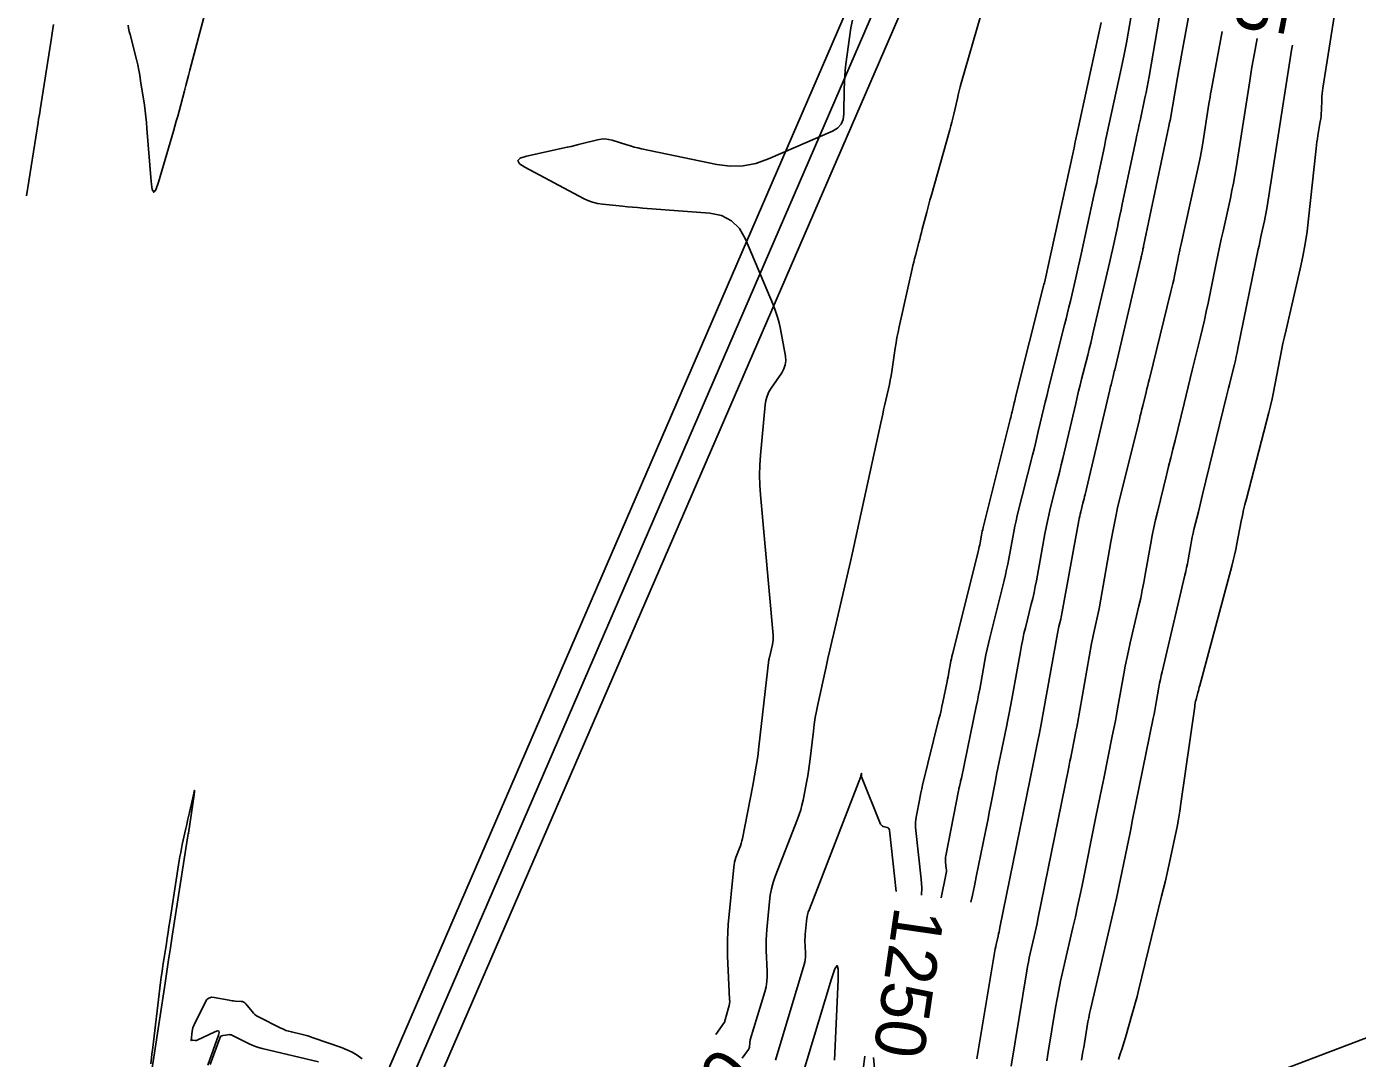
# Model space of a CAD drawing. Extents: x 658976 to 668721, y 639543 to 647196.
# Drawn here: x 661518.4 to 661677.1, y 641635 to 641758.1 of the extents above; entities that cross this region are included whole.
import ezdxf

# ---------------------------------------------------------------- set-up
doc = ezdxf.new("R2010")
doc.units = 0
for name, color, linetype in [('Ex_Contour Labels', 7, 'Continuous'), ('Ex_Major Contours', 7, 'Continuous'), ('Ex_Minor Contours', 7, 'Continuous'), ('R_Water', 7, 'Continuous')]:
    doc.layers.add(name, color=color, linetype=linetype)

msp = doc.modelspace()

# ---------------------------------------------------------------- linework, layer by layer
at = {"layer": 'Ex_Major Contours'}
for points in [[(661603.77, 641635.03), (661604.51, 641636.08), (661604.56, 641636.16), (661604.6, 641636.25), (661604.63, 641636.34), (661604.64, 641636.44), (661604.66, 641636.83), (661604.67, 641636.93), (661604.69, 641637.03), (661604.71, 641637.12), (661604.73, 641637.22), (661606.46, 641642.97), (661606.61, 641643.57), (661606.72, 641644.18), (661606.76, 641644.79), (661606.76, 641645.41), (661606.64, 641647.9), (661606.62, 641648.52), (661606.63, 641649.15), (661606.65, 641649.77), (661606.7, 641650.39), (661607.01, 641653.74), (661607.11, 641654.5), (661607.26, 641655.25), (661607.46, 641655.98), (661607.71, 641656.71), (661610.37, 641663.57), (661610.57, 641664.12), (661610.74, 641664.68), (661610.89, 641665.24), (661611.02, 641665.81), (661611.47, 641668.12), (661611.58, 641668.7), (661611.68, 641669.27), (661611.76, 641669.86), (661611.83, 641670.44), (661612.25, 641674.06), (661612.36, 641674.86), (661612.48, 641675.66), (661612.62, 641676.45), (661612.78, 641677.23), (661613.77, 641681.71), (661613.99, 641682.72), (661614.21, 641683.72), (661614.44, 641684.73), (661614.68, 641685.73), (661616.66, 641694.28), (661616.87, 641695.18), (661617.08, 641696.08), (661617.28, 641696.98), (661617.48, 641697.89), (661620.29, 641710.83), (661620.41, 641711.34), (661620.52, 641711.85), (661620.63, 641712.36), (661620.75, 641712.87), (661621.21, 641714.9), (661621.32, 641715.41), (661621.42, 641715.92), (661621.51, 641716.43), (661621.6, 641716.95), (661622.01, 641719.73), (661622.11, 641720.37), (661622.22, 641721), (661622.35, 641721.63), (661622.48, 641722.26), (661624.02, 641729.21), (661624.11, 641729.61), (661624.21, 641730), (661624.31, 641730.39), (661624.41, 641730.78), (661624.83, 641732.35), (661624.94, 641732.74), (661625.04, 641733.13), (661625.14, 641733.52), (661625.24, 641733.91), (661625.77, 641735.96), (661625.9, 641736.43), (661626.02, 641736.9), (661626.15, 641737.38), (661626.28, 641737.85), (661628.53, 641745.78), (661628.66, 641746.25), (661628.78, 641746.71), (661628.89, 641747.17), (661629, 641747.64), (661629.42, 641749.5), (661629.53, 641749.97), (661629.64, 641750.43), (661629.77, 641750.9), (661629.89, 641751.36), (661632.2, 641759.46)], [(661646.58, 641758.59), (661643.63, 641745.03), (661643.59, 641744.86), (661643.55, 641744.68), (661643.51, 641744.51), (661643.48, 641744.33), (661643.33, 641743.63), (661643.29, 641743.46), (661643.25, 641743.28), (661643.22, 641743.11), (661643.18, 641742.93), (661640.22, 641729.36), (661640.18, 641729.17), (661640.14, 641728.99), (661640.1, 641728.8), (661640.06, 641728.62), (661639.88, 641727.88), (661639.84, 641727.7), (661639.79, 641727.52), (661639.75, 641727.33), (661639.7, 641727.15), (661636.36, 641713.88), (661636.31, 641713.66), (661636.26, 641713.44), (661636.2, 641713.22), (661636.15, 641713), (661635.94, 641712.12), (661635.89, 641711.89), (661635.84, 641711.67), (661635.78, 641711.45), (661635.73, 641711.23), (661632.49, 641698.35), (661632.44, 641698.12), (661632.38, 641697.89), (661632.34, 641697.66), (661632.29, 641697.43), (661632.12, 641696.51), (661632.08, 641696.28), (661632.03, 641696.05), (661631.98, 641695.82), (661631.93, 641695.59), (661628.84, 641683.23), (661628.78, 641682.96), (661628.72, 641682.69), (661628.66, 641682.43), (661628.61, 641682.16), (661628.41, 641681.07), (661628.36, 641680.8), (661628.31, 641680.53), (661628.26, 641680.26), (661628.2, 641679.99), (661627.69, 641677.51), (661627.58, 641677.01), (661627.47, 641676.51), (661627.36, 641676.01), (661627.23, 641675.51), (661625.28, 641667.6), (661625.17, 641667.15), (661625.07, 641666.7), (661624.98, 641666.26), (661624.89, 641665.81), (661624.54, 641664), (661624.47, 641663.55), (661624.43, 641663.1), (661624.43, 641662.65), (661624.46, 641662.19), (661625.1, 641656.39), (661625.17, 641655.35), (661625.16, 641654.49)], [(661640.07, 641634.74), (661640.16, 641635.24), (661640.24, 641635.74), (661641.12, 641641.07), (661641.31, 641642.12), (661641.51, 641643.17), (661641.72, 641644.22), (661641.96, 641645.26), (661643.2, 641650.64), (661643.49, 641651.89), (661643.76, 641653.14), (661644.03, 641654.38), (661644.29, 641655.64), (661645.94, 641663.83), (661646.17, 641664.97), (661646.41, 641666.12), (661646.64, 641667.27), (661646.87, 641668.41), (661647.89, 641673.44), (661648.08, 641674.37), (661648.26, 641675.29), (661648.43, 641676.22), (661648.6, 641677.15), (661649.26, 641680.87), (661649.43, 641681.8), (661649.61, 641682.73), (661649.81, 641683.65), (661650.02, 641684.57), (661651.06, 641688.99), (661651.28, 641689.92), (661651.47, 641690.85), (661651.66, 641691.78), (661651.83, 641692.72), (661652.48, 641696.46), (661652.66, 641697.4), (661652.84, 641698.33), (661653.05, 641699.26), (661653.27, 641700.18), (661654.35, 641704.57), (661654.61, 641705.61), (661654.87, 641706.65), (661655.12, 641707.69), (661655.38, 641708.73), (661656.45, 641713.12), (661656.69, 641714.12), (661656.93, 641715.11), (661657.18, 641716.11), (661657.43, 641717.11), (661658.41, 641721.1), (661658.65, 641722.09), (661658.88, 641723.09), (661659.1, 641724.1), (661659.32, 641725.1), (661660.29, 641729.88), (661660.49, 641730.84), (661660.69, 641731.79), (661660.89, 641732.75), (661661.1, 641733.7), (661661.97, 641737.64), (661662.16, 641738.53), (661662.34, 641739.43), (661662.5, 641740.33), (661662.65, 641741.23), (661664.28, 641751.61), (661664.41, 641752.44), (661664.55, 641753.27), (661664.69, 641754.1), (661664.84, 641754.92), (661665.16, 641756.69)], [(661540.34, 641634.27), (661541.48, 641637.44), (661541.54, 641637.56), (661541.62, 641637.66), (661541.73, 641637.72), (661541.87, 641637.76), (661542.45, 641637.84), (661542.59, 641637.86), (661542.73, 641637.84), (661542.87, 641637.81), (661543, 641637.76), (661544.96, 641636.76), (661545.34, 641636.59), (661545.72, 641636.43), (661546.11, 641636.3), (661546.51, 641636.2), (661553.23, 641634.61)]]:
    msp.add_lwpolyline(points, dxfattribs=at)
at = {"layer": 'Ex_Minor Contours'}
for points in [[(661658.84, 641769.45), (661656.29, 641755.55), (661656.13, 641754.67), (661655.97, 641753.79), (661655.81, 641752.92), (661655.66, 641752.04), (661654.78, 641746.88), (661654.77, 641746.82), (661654.76, 641746.77), (661654.75, 641746.72), (661654.73, 641746.66), (661654.69, 641746.45), (661654.68, 641746.39), (661654.66, 641746.34), (661654.65, 641746.29), (661654.64, 641746.23), (661651.63, 641731.92), (661651.6, 641731.79), (661651.57, 641731.66), (661651.54, 641731.54), (661651.52, 641731.41), (661651.4, 641730.89), (661651.38, 641730.76), (661651.35, 641730.63), (661651.32, 641730.51), (661651.29, 641730.38), (661648.18, 641717.16), (661648.13, 641716.96), (661648.09, 641716.76), (661648.04, 641716.56), (661647.99, 641716.36), (661647.79, 641715.56), (661647.74, 641715.36), (661647.69, 641715.16), (661647.64, 641714.96), (661647.59, 641714.76), (661644.65, 641702.29), (661644.59, 641702.03), (661644.53, 641701.77), (661644.46, 641701.51), (661644.4, 641701.25), (661644.14, 641700.2), (661644.07, 641699.94), (661644.01, 641699.68), (661643.96, 641699.42), (661643.91, 641699.16), (661641.93, 641688.28), (661641.89, 641688.07), (661641.85, 641687.85), (661641.8, 641687.63), (661641.75, 641687.42), (661641.53, 641686.55), (661641.48, 641686.34), (661641.43, 641686.12), (661641.39, 641685.9), (661641.34, 641685.68), (661639.32, 641674.46), (661639.29, 641674.25), (661639.24, 641674.03), (661639.2, 641673.81), (661639.16, 641673.6), (661638.97, 641672.7), (661638.93, 641672.5), (661638.89, 641672.3), (661638.85, 641672.11), (661638.81, 641671.91), (661638.66, 641671.11), (661638.62, 641670.91), (661638.58, 641670.72), (661638.54, 641670.52), (661638.5, 641670.32), (661634.5, 641650.62), (661634.45, 641650.36), (661634.4, 641650.11), (661634.34, 641649.86), (661634.28, 641649.61), (661634.05, 641648.61), (661633.99, 641648.36), (661633.94, 641648.1), (661633.89, 641647.85), (661633.84, 641647.6), (661631.75, 641634.95)], [(661654.72, 641766.34), (661652.29, 641752.16), (661652.17, 641751.52), (661652.05, 641750.88), (661651.93, 641750.24), (661651.79, 641749.6), (661651.24, 641747.06), (661651.1, 641746.42), (661650.96, 641745.79), (661650.83, 641745.15), (661650.69, 641744.51), (661649.09, 641736.9), (661648.94, 641736.22), (661648.8, 641735.54), (661648.65, 641734.86), (661648.5, 641734.17), (661647.91, 641731.45), (661647.76, 641730.77), (661647.61, 641730.09), (661647.45, 641729.41), (661647.29, 641728.73), (661645.66, 641721.79), (661645.49, 641721.07), (661645.32, 641720.35), (661645.14, 641719.62), (661644.96, 641718.91), (661644.24, 641716.03), (661644.06, 641715.31), (661643.88, 641714.59), (661643.71, 641713.87), (661643.53, 641713.14), (661641.98, 641706.57), (661641.81, 641705.82), (661641.63, 641705.07), (661641.44, 641704.32), (661641.26, 641703.57), (661640.5, 641700.58), (661640.32, 641699.83), (661640.15, 641699.08), (661640, 641698.33), (661639.85, 641697.57), (661638.84, 641692), (661638.71, 641691.29), (661638.56, 641690.58), (661638.4, 641689.88), (661638.23, 641689.18), (661637.53, 641686.38), (661637.36, 641685.68), (661637.21, 641684.98), (661637.06, 641684.27), (661636.93, 641683.56), (661635.9, 641677.85), (661635.75, 641677.02), (661635.59, 641676.2), (661635.43, 641675.38), (661635.26, 641674.55), (661634.55, 641671.14), (661634.4, 641670.38), (661634.24, 641669.63), (661634.09, 641668.87), (661633.95, 641668.12), (661633.37, 641665.09), (661633.22, 641664.33), (661633.08, 641663.58), (661632.93, 641662.82), (661632.77, 641662.07), (661631.68, 641656.68), (661631.45, 641655.58), (661631.21, 641654.47), (661631.03, 641653.64)], [(661650.57, 641761.92), (661649.78, 641757.29), (661649.57, 641756.14), (661649.35, 641754.98), (661649.12, 641753.83), (661648.88, 641752.69), (661647.57, 641746.69), (661647.41, 641745.96), (661647.26, 641745.23), (661647.1, 641744.51), (661646.95, 641743.78), (661646.33, 641740.86), (661646.18, 641740.14), (661646.03, 641739.41), (661645.87, 641738.68), (661645.71, 641737.95), (661644.18, 641730.94), (661644.03, 641730.24), (661643.87, 641729.54), (661643.71, 641728.84), (661643.55, 641728.14), (661642.89, 641725.33), (661642.72, 641724.63), (661642.55, 641723.93), (661642.38, 641723.23), (661642.21, 641722.53), (661640.42, 641715.42), (661640.24, 641714.72), (661640.07, 641714.01), (661639.9, 641713.31), (661639.73, 641712.6), (661639.07, 641709.78), (661638.9, 641709.08), (661638.73, 641708.37), (661638.56, 641707.67), (661638.38, 641706.97), (661636.57, 641699.77), (661636.42, 641699.13), (661636.27, 641698.49), (661636.14, 641697.84), (661636.02, 641697.2), (661635.55, 641694.61), (661635.42, 641693.96), (661635.29, 641693.32), (661635.15, 641692.68), (661634.99, 641692.04), (661633.28, 641685.19), (661633.12, 641684.51), (661632.97, 641683.83), (661632.83, 641683.15), (661632.7, 641682.47), (661632.21, 641679.73), (661632.08, 641679.05), (661631.95, 641678.37), (661631.82, 641677.68), (661631.68, 641677), (661629.9, 641668.45), (661629.87, 641668.32), (661629.84, 641668.2), (661629.81, 641668.07), (661629.78, 641667.95), (661629.66, 641667.45), (661629.63, 641667.32), (661629.6, 641667.2), (661629.58, 641667.07), (661629.55, 641666.95), (661628.04, 641659.19), (661628.01, 641659), (661628, 641658.81), (661628, 641658.63), (661628.01, 641658.44), (661628.09, 641657.68), (661628.11, 641657.49), (661628.11, 641657.3), (661628.09, 641657.11), (661628.06, 641656.93), (661627.48, 641654.16)], [(661530.54, 641758.28), (661530.61, 641757.9), (661530.69, 641757.52), (661530.78, 641757.14), (661531.54, 641754.16), (661531.69, 641753.54), (661531.82, 641752.91), (661531.94, 641752.28), (661532.04, 641751.64), (661532.48, 641748.73), (661532.58, 641748.04), (661532.66, 641747.34), (661532.73, 641746.64), (661532.79, 641745.93), (661533.28, 641739.62), (661533.41, 641738.67), (661533.6, 641738.34), (661533.86, 641738.62), (661534.18, 641739.52), (661535.95, 641745.6), (661536.12, 641746.2), (661536.29, 641746.81), (661536.46, 641747.41), (661536.62, 641748.02), (661537.28, 641750.45), (661537.44, 641751.06), (661537.6, 641751.67), (661537.76, 641752.27), (661537.92, 641752.88), (661539.78, 641759.95)], [(661600.64, 641637.88), (661601.66, 641639.32), (661601.68, 641639.34), (661601.69, 641639.37), (661601.69, 641639.39), (661601.7, 641639.42), (661601.7, 641639.53), (661601.71, 641639.55), (661601.71, 641639.58), (661601.72, 641639.61), (661601.72, 641639.63), (661602.15, 641641.06), (661602.21, 641641.31), (661602.26, 641641.56), (661602.28, 641641.81), (661602.27, 641642.06), (661602.03, 641647.22), (661602, 641648.17), (661602.01, 641649.11), (661602.04, 641650.06), (661602.11, 641651), (661602.75, 641657.82), (661602.79, 641658.12), (661602.84, 641658.41), (661602.92, 641658.69), (661603.02, 641658.98), (661603.45, 641660.1), (661603.56, 641660.38), (661603.65, 641660.66), (661603.72, 641660.95), (661603.79, 641661.24), (661605.03, 641667.56), (661605.24, 641668.71), (661605.44, 641669.87), (661605.61, 641671.03), (661605.75, 641672.19), (661606.96, 641682.58), (661606.96, 641682.6), (661606.96, 641682.63), (661606.97, 641682.65), (661606.97, 641682.67), (661606.99, 641682.76), (661607, 641682.78), (661607, 641682.8), (661607.01, 641682.82), (661607.01, 641682.84), (661607.37, 641684.4), (661607.42, 641684.67), (661607.45, 641684.93), (661607.46, 641685.2), (661607.45, 641685.48), (661605.95, 641702.23), (661605.87, 641703.41), (661605.84, 641704.59), (661605.87, 641705.78), (661605.95, 641706.96), (661606.51, 641712.97), (661606.59, 641713.51), (661606.74, 641714.02), (661606.95, 641714.51), (661607.23, 641714.97), (661608.48, 641716.78), (661608.74, 641717.25), (661608.9, 641717.73), (661608.96, 641718.24), (661608.91, 641718.77), (661608.32, 641722.02), (661608.17, 641722.74), (661607.98, 641723.44), (661607.75, 641724.14), (661607.49, 641724.82), (661604.14, 641732.75), (661603.43, 641734), (661602.48, 641734.93), (661601.3, 641735.54), (661599.89, 641735.82), (661591.9, 641736.45), (661591.29, 641736.5), (661590.69, 641736.56), (661590.09, 641736.61), (661589.49, 641736.67), (661587.09, 641736.91), (661586.5, 641737), (661585.93, 641737.15), (661585.37, 641737.35), (661584.83, 641737.6), (661577.86, 641741.31), (661577.22, 641741.74), (661577.03, 641742.11), (661577.31, 641742.41), (661578.04, 641742.65), (661582.91, 641743.71), (661583.36, 641743.81), (661583.81, 641743.91), (661584.26, 641744.02), (661584.71, 641744.13), (661586.52, 641744.59), (661586.96, 641744.67), (661587.4, 641744.69), (661587.84, 641744.64), (661588.27, 641744.54), (661590.01, 641743.98), (661590.44, 641743.85), (661590.88, 641743.73), (661591.32, 641743.62), (661591.77, 641743.52), (661600.74, 641741.66), (661602.32, 641741.46), (661603.88, 641741.49), (661605.41, 641741.78), (661606.92, 641742.3), (661614.52, 641745.62), (661615.12, 641745.97), (661615.55, 641746.44), (661615.81, 641747.01), (661615.9, 641747.7), (661615.93, 641750.67), (661615.95, 641751.41), (661615.99, 641752.15), (661616.06, 641752.89), (661616.14, 641753.63), (661616.7, 641757.96), (661616.91, 641758.86)], [(661674.5, 641760.31), (661673, 641750.76), (661672.96, 641750.43), (661672.92, 641750.1), (661672.89, 641749.76), (661672.88, 641749.43), (661672.83, 641748.09), (661672.81, 641747.76), (661672.78, 641747.42), (661672.74, 641747.09), (661672.69, 641746.76), (661672.41, 641745.11), (661672.35, 641744.72), (661672.29, 641744.34), (661672.24, 641743.95), (661672.2, 641743.56), (661671.3, 641735.18), (661671.11, 641733.67), (661670.88, 641732.17), (661670.61, 641730.67), (661670.29, 641729.19), (661668.61, 641721.92), (661668.42, 641721.1), (661668.24, 641720.28), (661668.07, 641719.46), (661667.91, 641718.63), (661667.29, 641715.33), (661667.12, 641714.5), (661666.94, 641713.68), (661666.75, 641712.86), (661666.55, 641712.05), (661663.88, 641701.77), (661663.71, 641701.1), (661663.55, 641700.44), (661663.41, 641699.77), (661663.27, 641699.09), (661662.75, 641696.4), (661662.61, 641695.72), (661662.46, 641695.05), (661662.3, 641694.39), (661662.13, 641693.72), (661658.32, 641679.49), (661658.27, 641679.28), (661658.21, 641679.07), (661658.16, 641678.87), (661658.1, 641678.66), (661657.89, 641677.83), (661657.83, 641677.62), (661657.79, 641677.41), (661657.75, 641677.2), (661657.72, 641676.99), (661656.08, 641665.42), (661655.94, 641664.49), (661655.78, 641663.56), (661655.61, 641662.64), (661655.42, 641661.71), (661654.63, 641658.03), (661654.42, 641657.11), (661654.22, 641656.19), (661654, 641655.27), (661653.78, 641654.36), (661651.03, 641643.1), (661650.85, 641642.4), (661650.67, 641641.71), (661650.48, 641641.02), (661650.28, 641640.33), (661649.46, 641637.52), (661649.26, 641636.87), (661649.06, 641636.21), (661648.84, 641635.56), (661648.62, 641634.9)], [(661518.42, 641737.91), (661519.82, 641746.66), (661519.88, 641747.04), (661519.94, 641747.41), (661520, 641747.79), (661520.06, 641748.17), (661521.32, 641756.24), (661521.4, 641756.77), (661521.48, 641757.3), (661521.55, 641757.82), (661521.63, 641758.35)], [(661635.82, 641634.07), (661637.7, 641645.45), (661637.79, 641645.97), (661637.89, 641646.48), (661638, 641647), (661638.11, 641647.52), (661638.59, 641649.57), (661638.7, 641650.09), (661638.82, 641650.6), (661638.93, 641651.12), (661639.03, 641651.64), (661642.66, 641669.56), (661642.75, 641670.01), (661642.84, 641670.46), (661642.93, 641670.91), (661643.02, 641671.36), (661643.39, 641673.16), (661643.48, 641673.6), (661643.56, 641674.05), (661643.65, 641674.51), (661643.73, 641674.96), (661645.42, 641684.51), (661645.49, 641684.87), (661645.56, 641685.24), (661645.64, 641685.6), (661645.72, 641685.96), (661646.06, 641687.41), (661646.14, 641687.77), (661646.22, 641688.14), (661646.29, 641688.5), (661646.36, 641688.87), (661647.72, 641696.64), (661647.98, 641698.05), (661648.26, 641699.46), (661648.57, 641700.87), (661648.91, 641702.27), (661651.13, 641711.24), (661651.23, 641711.65), (661651.33, 641712.05), (661651.43, 641712.46), (661651.53, 641712.86), (661651.92, 641714.47), (661652.02, 641714.88), (661652.12, 641715.28), (661652.22, 641715.68), (661652.32, 641716.09), (661654.89, 641726.5), (661655, 641726.96), (661655.11, 641727.43), (661655.22, 641727.9), (661655.31, 641728.38), (661655.7, 641730.27), (661655.8, 641730.74), (661655.9, 641731.21), (661656, 641731.68), (661656.1, 641732.15), (661658.32, 641742.23), (661658.41, 641742.65), (661658.49, 641743.08), (661658.57, 641743.5), (661658.64, 641743.93), (661659.42, 641748.88), (661659.48, 641749.27), (661659.55, 641749.66), (661659.61, 641750.06), (661659.69, 641750.45), (661660.98, 641757.52)], [(661644.21, 641634.82), (661644.3, 641635.32), (661644.4, 641635.82), (661644.49, 641636.33), (661644.57, 641636.83), (661644.91, 641638.85), (661644.99, 641639.36), (661645.09, 641639.86), (661645.19, 641640.36), (661645.3, 641640.86), (661648.38, 641654.14), (661648.56, 641654.9), (661648.72, 641655.66), (661648.89, 641656.43), (661649.04, 641657.19), (661649.66, 641660.25), (661649.82, 641661.01), (661649.97, 641661.78), (661650.13, 641662.54), (661650.28, 641663.31), (661652.78, 641675.61), (661652.87, 641676.07), (661652.96, 641676.53), (661653.05, 641676.99), (661653.13, 641677.45), (661653.46, 641679.3), (661653.54, 641679.76), (661653.63, 641680.22), (661653.73, 641680.68), (661653.84, 641681.14), (661656.56, 641692.65), (661656.66, 641693.1), (661656.76, 641693.56), (661656.85, 641694.01), (661656.93, 641694.47), (661657.25, 641696.29), (661657.33, 641696.74), (661657.42, 641697.2), (661657.52, 641697.65), (661657.63, 641698.1), (661658.16, 641700.23), (661658.28, 641700.74), (661658.41, 641701.25), (661658.53, 641701.75), (661658.65, 641702.26), (661661.52, 641714), (661661.63, 641714.47), (661661.75, 641714.95), (661661.87, 641715.42), (661661.98, 641715.9), (661662.45, 641717.8), (661662.57, 641718.27), (661662.68, 641718.75), (661662.78, 641719.23), (661662.88, 641719.7), (661665.3, 641731.53), (661665.39, 641731.95), (661665.48, 641732.38), (661665.57, 641732.8), (661665.66, 641733.23), (661666.03, 641734.92), (661666.12, 641735.35), (661666.21, 641735.77), (661666.28, 641736.2), (661666.36, 641736.63), (661669.28, 641755.27), (661669.38, 641755.86)], [(661607.74, 641634.8), (661611.17, 641646.21), (661611.24, 641646.5), (661611.29, 641646.79), (661611.31, 641647.08), (661611.31, 641647.38), (661611.26, 641648.58), (661611.25, 641648.88), (661611.25, 641649.18), (661611.26, 641649.48), (661611.28, 641649.78), (661611.43, 641651.39), (661611.48, 641651.76), (661611.55, 641652.12), (661611.65, 641652.47), (661611.77, 641652.82), (661617.91, 641668.66), (661617.91, 641668.67), (661617.91, 641668.68), (661617.92, 641668.7), (661617.92, 641668.7), (661617.98, 641668.99), (661617.99, 641669.02), (661617.99, 641669.02), (661618, 641669.02), (661618, 641668.99), (661618, 641668.83), (661618, 641668.81), (661618, 641668.79), (661618, 641668.78), (661618, 641668.76), (661617.98, 641668.69), (661617.98, 641668.67), (661617.98, 641668.65), (661617.99, 641668.63), (661617.99, 641668.62), (661620.27, 641662.97), (661620.33, 641662.87), (661620.4, 641662.79), (661620.49, 641662.72), (661620.59, 641662.68), (661621.06, 641662.55), (661621.16, 641662.5), (661621.24, 641662.44), (661621.29, 641662.35), (661621.32, 641662.24), (661622.12, 641654.93)], [(661533.27, 641634.36), (661533.43, 641635.84), (661533.43, 641635.88), (661533.44, 641635.92), (661533.44, 641635.96), (661533.45, 641636), (661533.47, 641636.16), (661533.48, 641636.2), (661533.48, 641636.24), (661533.49, 641636.28), (661533.49, 641636.32), (661534.33, 641643.39), (661534.41, 641644.05), (661534.5, 641644.72), (661534.59, 641645.38), (661534.69, 641646.05), (661535.11, 641648.7), (661535.21, 641649.36), (661535.31, 641650.02), (661535.41, 641650.69), (661535.52, 641651.35), (661536.65, 641658.62), (661536.73, 641659.1), (661536.82, 641659.58), (661536.91, 641660.06), (661537.01, 641660.53), (661537.43, 641662.44), (661537.53, 641662.91), (661537.64, 641663.39), (661537.74, 641663.86), (661537.85, 641664.34), (661538.33, 641666.47), (661538.43, 641666.86), (661538.47, 641666.98), (661538.46, 641666.85), (661538.41, 641666.46), (661537.73, 641661.89), (661537.7, 641661.75), (661537.68, 641661.61), (661537.66, 641661.47), (661537.64, 641661.33), (661535.81, 641649.6), (661535.59, 641648.19), (661535.38, 641646.79), (661535.16, 641645.38), (661534.95, 641643.98), (661533.61, 641635.18), (661533.61, 641635.16), (661532.94, 641630.89)], [(661610.75, 641632.39), (661614.4, 641644.52), (661614.81, 641645.71), (661615.08, 641646.08), (661615.21, 641645.64), (661615.21, 641644.38), (661614.79, 641634.79)], [(661540.06, 641634.2), (661541.34, 641637.79), (661541.42, 641638.11), (661541.37, 641638.28), (661541.19, 641638.31), (661540.88, 641638.2), (661538.79, 641637.19), (661538.73, 641637.17), (661538.68, 641637.15), (661538.62, 641637.15), (661538.56, 641637.15), (661538.26, 641637.18), (661538.23, 641637.18), (661538.21, 641637.18), (661538.19, 641637.18), (661538.17, 641637.17), (661538.08, 641637.13), (661538.07, 641637.13), (661538.05, 641637.13), (661538.05, 641637.14), (661538.05, 641637.16), (661538.2, 641638.28), (661538.23, 641638.47), (661538.28, 641638.65), (661538.35, 641638.84), (661538.42, 641639.01), (661539.76, 641641.76), (661539.95, 641642.03), (661540.18, 641642.21), (661540.47, 641642.3), (661540.8, 641642.28), (661542.6, 641641.95), (661542.77, 641641.92), (661542.95, 641641.9), (661543.13, 641641.88), (661543.3, 641641.86), (661544.01, 641641.81), (661544.18, 641641.79), (661544.34, 641641.73), (661544.47, 641641.63), (661544.59, 641641.51), (661545.32, 641640.61), (661545.48, 641640.42), (661545.67, 641640.25), (661545.87, 641640.11), (661546.08, 641639.99), (661548.76, 641638.63), (661549.06, 641638.49), (661549.37, 641638.36), (661549.69, 641638.26), (661550.02, 641638.17), (661551.33, 641637.86), (661551.66, 641637.78), (661551.98, 641637.69), (661552.3, 641637.59), (661552.62, 641637.48), (661555.99, 641636.3), (661556.64, 641636.04), (661557.27, 641635.74), (661557.87, 641635.38), (661558.45, 641634.98)], [(661618.02, 641632.43), (661618.38, 641635.27)], [(661619.41, 641635.12), (661619.58, 641633.38)]]:
    msp.add_lwpolyline(points, dxfattribs=at)
at = {"layer": 'R_Water'}
for p, q in [((661564.22, 641594.16), (662140.69, 641813.25)), ((661536.1, 641567.27), (661639.64, 641806.63)), ((661540.52, 641585.06), (661636.89, 641807.82)), ((661556.63, 641607.19), (661642.4, 641805.44))]:
    msp.add_line(p, q, dxfattribs=at)

# ---------------------------------------------------------------- texts
at = {"layer": 'Ex_Contour Labels'}
for s, rotation, p in [('1255', 258.8215, (661665.78, 641775.26)), ('1250', 261.7271, (661621.96, 641653.27)), ('1250', 47.6107, (661593.62, 641619.46))]:
    msp.add_text(s, height=6, rotation=rotation, dxfattribs=at).set_placement(p)

doc.saveas('drawing.dxf')
